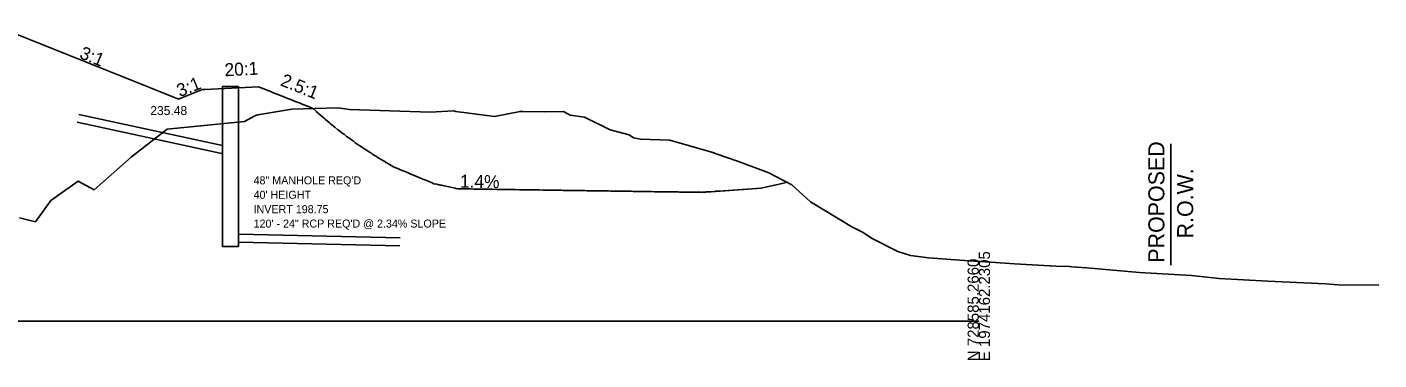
# Model space of a CAD drawing. Extents: x -26 to 1629, y -25 to 9635.
# Drawn here: x 312.2 to 650, y 5490.3 to 5573.5 of the extents above; entities that cross this region are included whole.
import ezdxf

# ---------------------------------------------------------------- set-up
doc = ezdxf.new("R2010")
doc.units = 0
for name, color, linetype in [('Default', 7, 'Continuous'), ('DTM CONTOURS_MAJOR', 7, 'Continuous'), ('DTM_X_GROUND', 7, 'Continuous'), ('XS_CELL', 7, 'Continuous'), ('XS_P_DRAINAGE', 7, 'Continuous'), ('XS_P_GROUND', 7, 'Continuous'), ('XS_P_ROW', 7, 'Continuous'), ('XS_P_TX_DCH', 7, 'Continuous'), ('XS_P_TX_FS_BS', 7, 'Continuous')]:
    doc.layers.add(name, color=color, linetype=linetype)

msp = doc.modelspace()

# ---------------------------------------------------------------- linework, layer by layer
at = {"layer": 'DTM_X_GROUND'}
msp.add_lwpolyline([(310.23, 5525.82), (314.24, 5524.82), (318.06, 5530.14), (324.93, 5535.01), (328.94, 5532.78), (338.16, 5540.98), (338.23, 5541.05), (347.2, 5547.93), (366.49, 5549.89), (369.07, 5551.26), (369.87, 5551.56), (378.33, 5552.97), (389.86, 5553.29), (392.77, 5552.85), (412.89, 5552.18), (418.77, 5552.51), (419.35, 5552.4), (420.52, 5552.24), (421.3, 5552.14), (428.94, 5551.16), (432.38, 5551.82), (435.38, 5552.39), (436.04, 5552.38), (441.35, 5552.29), (446.2, 5552.36), (447.86, 5551.43), (451.45, 5550.95), (457.89, 5547.82), (462.64, 5546.54), (463.73, 5545.77), (465.46, 5545.49), (472.82, 5545.25), (483.56, 5542.12), (484.64, 5541.75), (489.93, 5539.88), (497.51, 5537.04), (503.3, 5534.06), (507.9, 5529.8), (518.28, 5523.58), (520.9, 5522.26), (523.36, 5520.68), (529.79, 5517.38), (532.93, 5516.43), (537.46, 5515.85), (538.58, 5515.76), (547.5, 5515.1), (552.97, 5514.74), (558.94, 5514.32), (567.73, 5513.85), (567.93, 5513.83), (569.21, 5513.77), (572.67, 5513.68), (573.21, 5513.58), (576.97, 5513.31), (590.14, 5512.16), (603.17, 5511.39), (610.05, 5510.66), (622.25, 5509.96), (636.66, 5509.3), (640.82, 5509.01), (650, 5509.04)], dxfattribs=at)
at = {"layer": 'XS_CELL'}
msp.add_line((100, 5500), (550, 5500), dxfattribs=at)
at = {"layer": 'XS_P_DRAINAGE'}
for p, q in [((361, 5558.62), (361, 5518.62)), ((361, 5558.62), (365, 5558.62)), ((365, 5558.62), (365, 5518.62)), ((325.11, 5551.63), (361, 5543.89)), ((324.68, 5549.68), (361.14, 5541.82)), ((405.37, 5520.84), (365.05, 5521.75)), ((365, 5518.62), (361, 5518.62)), ((405.32, 5518.84), (365, 5519.75))]:
    msp.add_line(p, q, dxfattribs=at)
at = {"layer": 'XS_P_GROUND'}
for points in [[(305, 5573.48), (343.03, 5558.27), (344, 5557.88), (349.85, 5555.54), (350, 5555.48), (350.15, 5555.54), (356, 5557.88), (356.33, 5557.9), (356.56, 5557.91), (370, 5558.58), (371.37, 5558.04), (372.37, 5557.63), (372.41, 5557.62), (372.44, 5557.61), (373.45, 5557.2), (373.53, 5557.17), (376.6, 5555.94), (376.65, 5555.92), (378.7, 5555.1), (378.76, 5555.08), (380.82, 5554.26), (380.82, 5554.25), (381.29, 5554.06), (382.26, 5553.68), (382.28, 5553.67), (382.29, 5553.67), (382.38, 5553.63), (382.4, 5553.62), (382.45, 5553.6), (382.47, 5553.59), (382.88, 5553.43), (383.01, 5553.38), (383.06, 5553.36), (383.1, 5553.34), (383.15, 5553.32), (383.19, 5553.3), (383.24, 5553.28), (383.3, 5553.26), (383.43, 5553.21), (383.47, 5553.2), (383.59, 5553.14), (383.64, 5553.13), (383.65, 5553.12), (383.65, 5553.12)], [(383.64, 5553.13), (384.39, 5552.44), (384.44, 5552.4), (385.47, 5551.47), (385.6, 5551.38), (386.55, 5550.53), (386.75, 5550.39), (387.64, 5549.61), (387.91, 5549.42), (388.73, 5548.71), (389.07, 5548.48), (389.82, 5547.84), (390.23, 5547.57), (390.91, 5547), (391.38, 5546.69), (392, 5546.17), (392.54, 5545.82), (392.67, 5545.71), (392.81, 5545.63), (393.23, 5545.28), (393.7, 5544.99), (394.19, 5544.59), (394.86, 5544.17), (395.29, 5543.82), (396.01, 5543.38), (396.39, 5543.08), (397.17, 5542.6), (397.49, 5542.36), (398.33, 5541.85), (398.59, 5541.65), (399.49, 5541.12), (399.69, 5540.96), (400.64, 5540.4), (400.79, 5540.29), (401.8, 5539.71), (401.84, 5539.68), (402.2, 5539.47), (402.22, 5539.46), (402.45, 5539.33), (402.46, 5539.32), (402.69, 5539.19), (402.7, 5539.18), (402.96, 5539.03), (403, 5539), (403.9, 5538.49), (404.09, 5538.41), (404.12, 5538.41), (405.13, 5537.98), (405.27, 5537.92), (406.17, 5537.55), (406.43, 5537.44), (407.2, 5537.12), (407.59, 5536.96), (408.24, 5536.68), (408.75, 5536.47), (409.28, 5536.25), (409.9, 5535.99), (410.31, 5535.82), (411.06, 5535.51), (411.35, 5535.39), (412.22, 5535.02), (412.39, 5534.95), (413.38, 5534.54), (413.42, 5534.52), (413.83, 5534.35)], [(419.78, 5533.07), (419.27, 5533.18), (419.17, 5533.2), (419.02, 5533.23), (418.01, 5533.45), (417.58, 5533.54), (416.85, 5533.7), (416.36, 5533.8), (415.69, 5533.95), (415.39, 5534.01), (414.54, 5534.2), (413.83, 5534.35)], [(501.85, 5534.66), (499.01, 5533.98), (498.98, 5533.97), (495.62, 5533.26), (495.57, 5533.25), (494.51, 5533.17), (494.41, 5533.16), (493.37, 5533.09), (493.25, 5533.08), (492.22, 5533.01), (492.09, 5533), (491.08, 5532.93), (490.94, 5532.91), (489.94, 5532.84), (489.78, 5532.83), (488.79, 5532.76), (488.62, 5532.75), (487.64, 5532.68), (487.46, 5532.67), (486.5, 5532.6), (486.31, 5532.58), (485.35, 5532.51), (485.15, 5532.5), (484.29, 5532.44), (484.09, 5532.42), (484.01, 5532.42), (483.99, 5532.42), (483.06, 5532.35), (482.83, 5532.33), (481.92, 5532.27), (481.68, 5532.25), (480.96, 5532.2), (480.75, 5532.18), (480.57, 5532.19), (480.52, 5532.19), (479.63, 5532.2), (479.36, 5532.2), (478.48, 5532.22), (478.2, 5532.22), (477.34, 5532.23), (477.05, 5532.24), (476.19, 5532.25), (475.89, 5532.25), (475.39, 5532.26), (475.21, 5532.26), (474.86, 5532.27), (474.73, 5532.27), (473.9, 5532.28), (473.57, 5532.29), (472.75, 5532.3), (472.42, 5532.3), (471.61, 5532.32), (471.26, 5532.32), (470.46, 5532.33), (470.1, 5532.34), (469.32, 5532.35), (468.94, 5532.35), (468.17, 5532.37), (467.79, 5532.37), (467.02, 5532.38), (466.63, 5532.39), (466.43, 5532.39), (466.33, 5532.39), (465.77, 5532.4), (465.47, 5532.4), (464.74, 5532.41), (464.31, 5532.42), (463.6, 5532.43), (463.15, 5532.44), (462.46, 5532.45), (462, 5532.45), (461.32, 5532.46), (460.84, 5532.47), (460.18, 5532.48), (459.68, 5532.49), (459.05, 5532.5), (458.52, 5532.5), (457.95, 5532.51), (457.44, 5532.52), (457.4, 5532.52), (457.37, 5532.52), (456.77, 5532.53), (456.21, 5532.54), (455.62, 5532.55), (455.05, 5532.55), (454.44, 5532.56), (453.89, 5532.57), (453.26, 5532.58), (452.74, 5532.59), (452.08, 5532.6), (451.58, 5532.61), (450.9, 5532.62), (450.42, 5532.62), (449.71, 5532.63), (449.26, 5532.64), (448.82, 5532.65), (448.56, 5532.65), (448.27, 5532.65), (448.11, 5532.66), (447.35, 5532.67), (446.95, 5532.67), (446.16, 5532.68), (445.79, 5532.69), (444.98, 5532.7), (444.63, 5532.71), (443.8, 5532.72), (443.48, 5532.72), (442.61, 5532.73), (442.32, 5532.74), (441.43, 5532.75), (441.16, 5532.76), (440.25, 5532.77), (440, 5532.77), (439.75, 5532.78), (439.68, 5532.78), (439, 5532.79), (438.85, 5532.79), (437.88, 5532.8), (437.69, 5532.81), (436.69, 5532.82), (436.53, 5532.82), (435.51, 5532.84), (435.37, 5532.84), (435.24, 5532.84), (434.21, 5532.86), (433.14, 5532.87), (433.06, 5532.87), (432.98, 5532.87), (431.9, 5532.89), (431.85, 5532.89), (430.8, 5532.91), (430.8, 5532.91), (430.74, 5532.91), (429.71, 5532.92), (429.58, 5532.92), (429.57, 5532.92), (428.43, 5532.94), (428.26, 5532.94), (427.27, 5532.96), (426.95, 5532.96), (426.11, 5532.97), (425.64, 5532.98), (424.95, 5532.99), (424.33, 5533), (423.8, 5533.01), (423.02, 5533.02), (422.64, 5533.02), (422.09, 5533.03), (421.92, 5533.03), (421.56, 5533.04), (421.48, 5533.04), (420.39, 5533.06), (420.32, 5533.06), (419.78, 5533.07)]]:
    msp.add_lwpolyline(points, dxfattribs=at)
at = {"layer": 'XS_P_ROW'}
msp.add_line((598, 5544.3), (598, 5513.98), dxfattribs=at)

# ---------------------------------------------------------------- texts
at = {"layer": 'Default'}
for p in [(399.04, 5546.74), (419.75, 5533.01)]:
    msp.add_text('X', height=0.12, dxfattribs=at).set_placement(p)
at = {"layer": 'DTM CONTOURS_MAJOR'}
for p in [(343.96, 5557.82), (355.96, 5557.82), (369.96, 5558.52), (349.96, 5555.42), (383.61, 5553.06), (386.58, 5551.91), (394.37, 5547.93), (394.37, 5547.93), (413.79, 5534.29), (429.67, 5532.86)]:
    msp.add_text('X', height=0.12, dxfattribs=at).set_placement(p)
at = {"layer": 'XS_CELL'}
for s, p in [('E 1974162.2305', (552.8, 5490)), ('N 728585.2660', (550, 5490))]:
    msp.add_text(s, height=2.8, rotation=90, dxfattribs=at).set_placement(p)
at = {"layer": 'XS_P_DRAINAGE'}
for s, p in [('48" MANHOLE REQ\'D', (368.77, 5534.18)), ("40' HEIGHT", (368.77, 5530.58)), ('INVERT 198.75', (368.77, 5526.98)), ('120\' - 24" RCP REQ\'D @ 2.34% SLOPE', (368.77, 5523.38))]:
    msp.add_text(s, height=2, dxfattribs=at).set_placement(p)
at = {"layer": 'XS_P_ROW'}
for s, p in [('PROPOSED', (596.37, 5514.61)), ('R.O.W.', (603.57, 5520.68))]:
    msp.add_text(s, height=4, rotation=90, dxfattribs=at).set_placement(p)
at = {"layer": 'XS_P_TX_DCH'}
msp.add_text('235.48', height=2.25, dxfattribs=at).set_placement((342.96, 5551.49))
at = {"layer": 'XS_P_TX_FS_BS'}
for s, rotation, p in [('3:1', 338.1986, (325.05, 5565.78)), ('20:1', 2.8624, (361.59, 5561.17)), ('2.5:1', 338.1986, (375.25, 5558.95)), ('3:1', 21.8014, (350.33, 5555.94)), ('1.4%', 359.1711, (420.33, 5533.36))]:
    msp.add_text(s, height=3.24, rotation=rotation, dxfattribs=at).set_placement(p)

doc.saveas('drawing.dxf')
